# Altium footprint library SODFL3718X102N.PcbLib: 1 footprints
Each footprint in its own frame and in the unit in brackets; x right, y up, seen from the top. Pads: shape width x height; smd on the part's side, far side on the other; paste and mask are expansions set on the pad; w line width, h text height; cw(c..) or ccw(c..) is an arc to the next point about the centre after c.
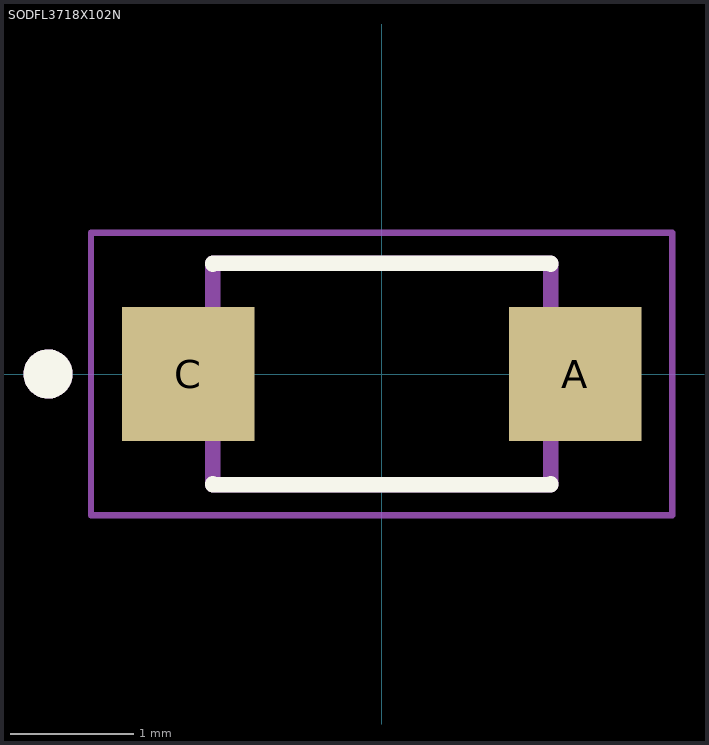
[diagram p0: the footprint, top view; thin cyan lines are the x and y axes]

## SODFL3718X102N [mm]
height 1.02
pads (2):
  rect 1.08x1.09 smd: A(1.575,0) C(-1.575,0)
Top Overlay:
  circle w0.2: c-2.715,0 r0.1
  lines w0.127: -1.375,-0.895 -1.375,-0.9 1.375,-0.9 1.375,-0.895 ; -1.375,0.895 -1.375,0.9 1.375,0.9 1.375,0.895
Mechanical 13:
  circle w0.2: c-2.715,0 r0.1
  lines w0.127: -1.375,-0.9 -1.375,0.9 1.375,0.9 1.375,-0.9 -1.375,-0.9
Mechanical 15:
  lines w0.05: -2.365,-1.15 -2.365,1.15 2.365,1.15 2.365,-1.15 -2.365,-1.15
3D body "TSSW3U60.step": height 1.03, standoff 0.01, extent -1.85,-0.9 1.85,0.9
